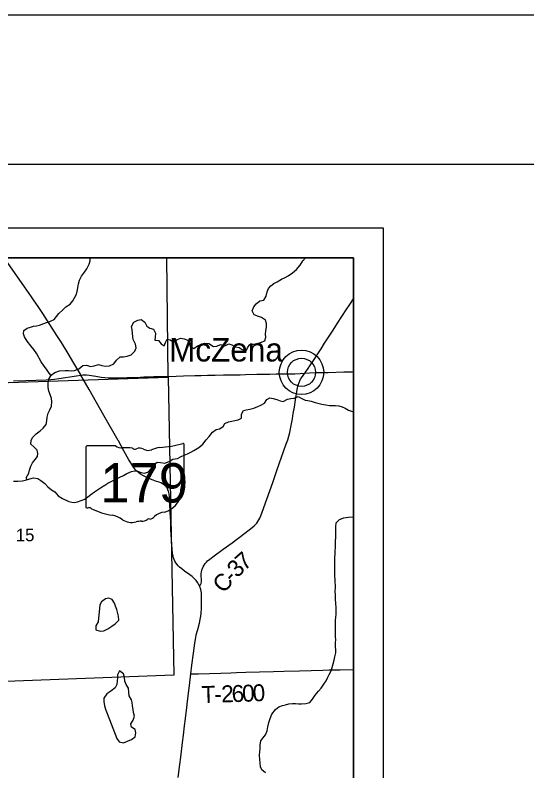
# Model space of a CAD drawing. Extents: x 0 to 34, y 0 to 22.
# Drawn here: x 7.526 to 9.242, y 19.466 to 22 of the extents above; entities that cross this region are included whole.
import ezdxf

# ---------------------------------------------------------------- set-up
doc = ezdxf.new("R2010")
doc.units = 0
for name, color, linetype in [('GM_X_Corporation', 7, 'Continuous'), ('GM_X_Corporation_Text', 7, 'Continuous'), ('GM_X_County_Road', 7, 'Continuous'), ('GM_X_County_Road_Text', 7, 'Continuous'), ('GM_X_Interchange_Ramps', 7, 'Continuous'), ('GM_X_Major_River_Text', 7, 'Continuous'), ('GM_X_Minor_River_Text', 7, 'Continuous'), ('GM_X_Rail_Line', 7, 'Continuous'), ('GM_X_Section_Text', 7, 'Continuous'), ('GM_X_State_Location', 7, 'Continuous'), ('GM_X_State_Route', 7, 'Continuous'), ('GM_X_Township_Road', 7, 'Continuous'), ('GM_X_Township_Text', 7, 'Continuous'), ('SH_Border', 7, 'Continuous'), ('SH_Cut_Line', 7, 'Continuous'), ('SH_Data', 7, 'Continuous')]:
    doc.layers.add(name, color=color, linetype=linetype)

msp = doc.modelspace()

# ---------------------------------------------------------------- linework, layer by layer
at = {"layer": 'GM_X_Corporation_Text'}
msp.add_line((8.4865, 20.8023), (8.4865, 20.8023), dxfattribs=at)
at = {"layer": 'GM_X_County_Road'}
for p, q in [((7.7634, 20.5519), (7.7634, 20.3518)), ((7.8632, 20.5554), (7.7666, 20.5554)), ((8.093, 20.4556), (8.093, 20.5603)), ((8.0929, 20.4557), (8.093, 20.4556))]:
    msp.add_line(p, q, dxfattribs=at)
for points in [[(7.8725, 20.5724), (7.8715, 20.5742), (7.824, 20.658), (7.7993, 20.7011), (7.7747, 20.7444), (7.7546, 20.7794), (7.7468, 20.793), (7.7453, 20.7956), (7.7234, 20.8332), (7.7041, 20.8651), (7.6814, 20.9022), (7.6667, 20.9259), (7.6194, 20.999), (7.6056, 21.0197), (7.5883, 21.0455), (7.5814, 21.0558), (7.5582, 21.0889), (7.5403, 21.1143), (7.5187, 21.1447), (7.5008, 21.17), (7.4888, 21.1866)], [(8.0729, 19.4442), (8.0782, 19.4873), (8.0814, 19.512), (8.0874, 19.5614), (8.0905, 19.586), (8.0942, 19.6169), (8.0973, 19.6415), (8.1016, 19.6785), (8.1044, 19.7001), (8.1109, 19.7525), (8.1156, 19.791), (8.1192, 19.8204), (8.1245, 19.8604), (8.1289, 19.8944), (8.1318, 19.9128), (8.1337, 19.922), (8.1384, 19.9401), (8.1442, 19.961), (8.1471, 19.9731), (8.1493, 19.9852), (8.1504, 19.9944), (8.1512, 20.0099), (8.1516, 20.0347), (8.1514, 20.0534), (8.1509, 20.0626), (8.1501, 20.0687), (8.1488, 20.0747), (8.1469, 20.0805), (8.1449, 20.0857), (8.1416, 20.0915), (8.1384, 20.0968), (8.1329, 20.1043), (8.1289, 20.1089), (8.1246, 20.1132), (8.1199, 20.1173), (8.1125, 20.1228), (8.0948, 20.1354), (8.0849, 20.143), (8.0777, 20.1491), (8.0733, 20.1535), (8.0692, 20.1583), (8.0655, 20.1634), (8.0622, 20.1688), (8.0595, 20.1745), (8.0573, 20.1804), (8.0557, 20.1864), (8.054, 20.1957), (8.0526, 20.2081), (8.0514, 20.2267), (8.0497, 20.2577), (8.0488, 20.2763), (8.0479, 20.3012), (8.0463, 20.3322), (8.0449, 20.3633), (8.0438, 20.385), (8.0428, 20.3942), (8.0417, 20.4002), (8.0409, 20.4031), (8.0387, 20.4088), (8.0374, 20.4116), (8.0358, 20.4142), (8.0341, 20.4167), (8.0323, 20.4191), (8.028, 20.4234), (8.0257, 20.4254), (8.0207, 20.4288), (8.0152, 20.4316), (8.0095, 20.4339), (8.0007, 20.4368), (7.9888, 20.4404), (7.9801, 20.4436), (7.9715, 20.4473), (7.9632, 20.4516), (7.955, 20.4563), (7.9472, 20.4614), (7.9397, 20.467), (7.935, 20.4712), (7.9305, 20.4756), (7.9265, 20.4804), (7.9209, 20.4879), (7.9141, 20.4984), (7.9078, 20.5092), (7.8912, 20.5389), (7.8725, 20.5724)]]:
    msp.add_lwpolyline(points, dxfattribs=at)
for centre, major_axis, start_param, end_param in [((7.7672, 20.5523), (0.00382, 0), 1.712693, 3.28349), ((7.8861, 20.5786), (0.037, 0), 4.042523, 4.731795), ((7.9756, 20.8282), (0.3495, 0), 4.814394, 5.042369), ((8.0893, 20.5608), (0.00367, 0), 6.141152, 7.989035), ((7.8984, 20.443), (0.133, 0), 1.404758, 1.657858), ((7.9286, 20.5534), (0.0107, 0), 3.836095, 5.185415), ((7.9443, 20.5302), (0.0222, 0), 0.950623, 2.079405), ((7.973, 20.562), (0.0267, 0), 4.081561, 5.145723), ((8.0201, 20.4942), (0.0703, 0), 1.699011, 2.107814), ((8.0921, 20.4479), (0.00568, 0), 1.883978, 3.671073), ((8.0891, 20.4552), (0.00393, 0), 5.05454, 6.418171), ((8.1061, 20.4118), (0.0248, 0), 2.387724, 3.262537), ((8.056, 20.4347), (0.0341, 0), 5.934695, 6.695948), ((7.9951, 20.3985), (0.0874, 0), 5.101752, 6.440018), ((7.7672, 20.3514), (0.00385, 0), 3.00124, 4.508301), ((7.7678, 20.3718), (0.0294, 0), 4.665946, 4.897461), ((7.7738, 20.3402), (0.0106, 0), 0.519207, 1.627899), ((7.9076, 20.52), (0.2524, 0), 4.195997, 4.488961), ((7.8324, 20.2619), (0.079, 0), 0.823519, 1.323587), ((8.032, 20.2956), (0.0479, 0), 1.647645, 2.488434), ((7.9178, 20.3393), (0.0501, 0), 4.026481, 4.996735), ((7.9467, 20.2701), (0.0412, 0), 1.495662, 1.94098), ((7.9504, 20.3243), (0.0267, 0), 4.691044, 5.507374), ((7.9746, 20.3049), (0.00752, 0), 1.147584, 2.315152), ((7.9713, 20.3324), (0.0282, 0), 4.937069, 5.64225)]:
    msp.add_ellipse(centre, major_axis=major_axis, ratio=0.8, start_param=start_param, end_param=end_param, dxfattribs=at)
at = {"layer": 'GM_X_County_Road_Text'}
msp.add_line((8.6543, 20.6725), (8.6602, 20.6699), dxfattribs=at)
for points in [[(7.6468, 20.7918), (7.6404, 20.7996), (7.6316, 20.8132), (7.624, 20.8234), (7.6133, 20.8374), (7.5988, 20.8647), (7.5889, 20.8783), (7.5786, 20.8912), (7.5664, 20.9063), (7.5576, 20.9211), (7.5549, 20.9317), (7.556, 20.9427), (7.5666, 20.9507), (7.5779, 20.9542), (7.5882, 20.9569), (7.5984, 20.958), (7.6086, 20.9607), (7.6222, 20.9657), (7.6321, 20.9692), (7.6423, 20.973), (7.6574, 20.9795), (7.6657, 20.989), (7.6733, 20.9997), (7.6857, 21.0107), (7.697, 21.0218), (7.711, 21.031), (7.7197, 21.0416), (7.7257, 21.0523), (7.7306, 21.0618), (7.734, 21.0732), (7.7366, 21.0861), (7.7388, 21.0986), (7.7425, 21.1108), (7.7485, 21.1252), (7.7591, 21.1385), (7.7666, 21.1488), (7.7749, 21.1652), (7.7779, 21.1766), (7.7775, 21.1866)], [(8.3252, 20.8966), (8.3354, 20.8986), (8.3494, 20.9021), (8.363, 20.9082), (8.3671, 20.9203), (8.3663, 20.9306), (8.3674, 20.9416), (8.3693, 20.9534), (8.3692, 20.9663), (8.3658, 20.9773), (8.3528, 20.9856), (8.3422, 20.9897), (8.3282, 20.9953), (8.3209, 21.0082), (8.3262, 21.0219), (8.3348, 21.0325), (8.3469, 21.0421), (8.3602, 21.0444), (8.3681, 21.0581), (8.3718, 21.0722), (8.3759, 21.0832), (8.3831, 21.0927), (8.3933, 21.0996), (8.4046, 21.1053), (8.4194, 21.1145), (8.4319, 21.1202), (8.4417, 21.1263), (8.4561, 21.1355), (8.4697, 21.1469), (8.4821, 21.1621), (8.4904, 21.1762), (8.4993, 21.1866)], [(7.5671, 20.4423), (7.5634, 20.449), (7.5724, 20.4646), (7.5742, 20.4741), (7.5795, 20.4874), (7.5851, 20.4984), (7.5942, 20.5102), (7.601, 20.5205), (7.6028, 20.5307), (7.6009, 20.5414), (7.5887, 20.5527), (7.5788, 20.5618), (7.5799, 20.5735), (7.5848, 20.5838), (7.5965, 20.5956), (7.6101, 20.6059), (7.621, 20.6151), (7.6305, 20.6276), (7.6331, 20.6401), (7.6338, 20.6515), (7.6375, 20.6652), (7.6428, 20.6766), (7.6484, 20.6888), (7.6495, 20.7043), (7.6479, 20.7142), (7.6456, 20.7244), (7.6399, 20.7388), (7.6368, 20.751), (7.6371, 20.7658), (7.6397, 20.7791), (7.6476, 20.7931), (7.6593, 20.8019), (7.6752, 20.8073), (7.6945, 20.8085), (7.7055, 20.8082), (7.7161, 20.8078), (7.726, 20.8082), (7.74, 20.8144), (7.7532, 20.8247), (7.7653, 20.8258), (7.7797, 20.8221), (7.7915, 20.8244), (7.8055, 20.8287), (7.8176, 20.8253), (7.8294, 20.8234), (7.843, 20.8242), (7.8574, 20.8311), (7.8664, 20.8433), (7.8785, 20.8547), (7.8895, 20.8548), (7.902, 20.856), (7.916, 20.8606), (7.9277, 20.8735), (7.9318, 20.8842), (7.9295, 20.8967), (7.9222, 20.9122), (7.9207, 20.9217), (7.9199, 20.9331), (7.9187, 20.9456), (7.9171, 20.9558), (7.9239, 20.9703), (7.9383, 20.9775), (7.9492, 20.9795), (7.9614, 20.9704), (7.9679, 20.9575), (7.9782, 20.95), (7.9907, 20.947), (7.9968, 20.9337), (7.9954, 20.9201), (7.9946, 20.9102), (8.0075, 20.9095), (8.0159, 20.8974), (8.0262, 20.8906), (8.0311, 20.902), (8.0356, 20.9134), (8.0462, 20.9115), (8.0568, 20.9047), (8.0693, 20.912), (8.0818, 20.9166), (8.0935, 20.9147), (8.1049, 20.9106), (8.1103, 20.9), (8.1133, 20.8894), (8.1251, 20.8822), (8.1376, 20.8914), (8.1516, 20.8956), (8.1626, 20.8998), (8.1758, 20.8995), (8.191, 20.8893), (8.2024, 20.8905), (8.2153, 20.8951), (8.2289, 20.891), (8.2433, 20.8982), (8.2528, 20.8949), (8.2657, 20.8881), (8.2775, 20.8858), (8.2873, 20.8787), (8.3006, 20.8749), (8.3059, 20.8844), (8.313, 20.8955), (8.3252, 20.8966)], [(7.5213, 20.4375), (7.5361, 20.4371), (7.5513, 20.4383), (7.5642, 20.4414), (7.5763, 20.4453), (7.5876, 20.4487), (7.6028, 20.4461), (7.6127, 20.4397), (7.626, 20.4291), (7.6366, 20.4189), (7.6484, 20.408), (7.6598, 20.4012), (7.6712, 20.3887), (7.6849, 20.3796), (7.7062, 20.3691), (7.7161, 20.3665), (7.7255, 20.3661), (7.7361, 20.3684), (7.7479, 20.3727), (7.7596, 20.3773), (7.7702, 20.3853), (7.7804, 20.3925), (7.7925, 20.402), (7.8027, 20.4085), (7.8125, 20.415), (7.8269, 20.4242), (7.8378, 20.4311), (7.8503, 20.4376), (7.8632, 20.4437), (7.8775, 20.4506), (7.8896, 20.4559), (7.9014, 20.4628), (7.9161, 20.4701), (7.9267, 20.472), (7.9362, 20.4705), (7.9491, 20.4664), (7.9586, 20.4641), (7.9718, 20.468), (7.9831, 20.4813), (7.9903, 20.492), (8.0031, 20.5007), (8.0141, 20.5004), (8.0278, 20.4978), (8.0429, 20.5036), (8.0554, 20.5108), (8.0706, 20.5139), (8.083, 20.5196), (8.0936, 20.5242), (8.1046, 20.5288), (8.1156, 20.535), (8.1254, 20.5403), (8.142, 20.5502), (8.1552, 20.562), (8.1669, 20.5757), (8.1764, 20.5876), (8.1877, 20.6016), (8.2001, 20.6108), (8.2115, 20.6123), (8.2236, 20.6207), (8.2296, 20.6306), (8.2421, 20.6364), (8.2531, 20.6387), (8.2633, 20.641), (8.2743, 20.6433), (8.2849, 20.6491), (8.2856, 20.662), (8.2916, 20.6738), (8.3014, 20.6764), (8.3128, 20.6784), (8.3264, 20.6822), (8.3401, 20.688), (8.3506, 20.6918), (8.3624, 20.6987), (8.3699, 20.7112), (8.3805, 20.7166), (8.3911, 20.7144), (8.4036, 20.711), (8.4154, 20.7072), (8.4253, 20.7042), (8.4392, 20.7123), (8.451, 20.7146), (8.4623, 20.7161), (8.4756, 20.7215), (8.4858, 20.7155), (8.4984, 20.7087), (8.5079, 20.708), (8.5185, 20.7061), (8.5318, 20.7012), (8.5416, 20.6986), (8.5545, 20.696), (8.5682, 20.6938), (8.5799, 20.6915), (8.5898, 20.6908), (8.6004, 20.6909), (8.6114, 20.6901), (8.6224, 20.6868), (8.6323, 20.6822), (8.6437, 20.6751), (8.6543, 20.6725)], [(8.6019, 19.8617), (8.6011, 19.8715), (8.6003, 19.8821), (8.6006, 19.895), (8.601, 19.9064), (8.6009, 19.9159), (8.6007, 19.9709), (8.6014, 19.9804), (8.6021, 19.9918), (8.6025, 20.0032), (8.6024, 20.0142), (8.6012, 20.0271), (8.6004, 20.0419), (8.6, 20.0567), (8.5995, 20.0681), (8.5999, 20.0802), (8.5998, 20.1064), (8.5986, 20.1193), (8.5985, 20.1322), (8.5981, 20.1432), (8.5979, 20.18), (8.599, 20.1945), (8.5994, 20.2047), (8.6001, 20.2142), (8.6, 20.2244), (8.6008, 20.2351), (8.6018, 20.2491), (8.6014, 20.2632), (8.601, 20.2749), (8.6017, 20.2848), (8.6028, 20.2973), (8.6133, 20.3091), (8.6281, 20.3141), (8.6436, 20.3168), (8.6592, 20.3173), (8.6602, 20.3172)], [(8.3656, 19.46), (8.3538, 19.4698), (8.3488, 19.4801), (8.348, 19.493), (8.3468, 19.5047), (8.3452, 19.5172), (8.3467, 19.5305), (8.3482, 19.54), (8.3481, 19.5522), (8.35, 19.5662), (8.3567, 19.5757), (8.3658, 19.5872), (8.3714, 19.6005), (8.374, 19.6134), (8.3774, 19.6278), (8.3811, 19.6415), (8.3871, 19.6567), (8.3988, 19.6719), (8.4109, 19.6811), (8.423, 19.6849), (8.4332, 19.688), (8.4442, 19.6907), (8.4563, 19.6919), (8.4662, 19.6915), (8.4768, 19.6908), (8.4866, 19.6904), (8.501, 19.6916), (8.5143, 19.6955), (8.523, 19.7061), (8.532, 19.7195), (8.5429, 19.7332), (8.552, 19.7431), (8.561, 19.7564), (8.5686, 19.7682), (8.575, 19.78), (8.5795, 19.7895), (8.5843, 19.7994), (8.5888, 19.8123), (8.5926, 19.8248), (8.5959, 19.8377), (8.5978, 19.848), (8.6019, 19.8617)]]:
    msp.add_lwpolyline(points, dxfattribs=at)
at = {"layer": 'GM_X_Interchange_Ramps'}
msp.add_lwpolyline([(8.1156, 19.791), (8.1222, 19.7911), (8.1409, 19.7914), (8.1782, 19.7926), (8.2155, 19.7939), (8.2497, 19.7953), (8.2683, 19.7958), (8.2994, 19.7967), (8.346, 19.7978), (8.3927, 19.7989), (8.4269, 19.8), (8.4797, 19.8015), (8.5575, 19.8038), (8.5792, 19.8045), (8.6166, 19.8052), (8.6602, 19.8064)], dxfattribs=at)
at = {"layer": 'GM_X_Minor_River_Text'}
for points in [[(7.8052, 19.9661), (7.7973, 19.9524), (7.797, 19.9387), (7.8114, 19.935), (7.8236, 19.9361), (7.8376, 19.9423), (7.8504, 19.9514), (7.8617, 19.9594), (7.8742, 19.9716), (7.8734, 19.9853), (7.8699, 19.9978), (7.8672, 20.0073), (7.863, 20.0186), (7.8596, 20.0281), (7.8516, 20.0406), (7.8409, 20.0451), (7.8292, 20.0428), (7.8156, 20.0325), (7.8103, 20.0222)], [(7.8103, 20.0222), (7.8052, 19.9661)], [(7.8675, 19.575), (7.8755, 19.5629), (7.8903, 19.5596), (7.9035, 19.5653), (7.9164, 19.5714), (7.9292, 19.5806), (7.9315, 19.5939), (7.9291, 19.6045), (7.9162, 19.6124), (7.9139, 19.6234), (7.9226, 19.6363), (7.9267, 19.6489), (7.9236, 19.6614), (7.922, 19.6716), (7.9201, 19.6841), (7.9185, 19.6948), (7.9166, 19.7042), (7.909, 19.7175), (7.9082, 19.73), (7.907, 19.7429), (7.8986, 19.7558), (7.894, 19.7671), (7.8936, 19.7793), (7.8893, 19.7918), (7.8764, 19.8012), (7.87, 19.7883), (7.8697, 19.7784), (7.869, 19.7667), (7.8675, 19.756), (7.8619, 19.7446), (7.8475, 19.7328), (7.8343, 19.7248), (7.8237, 19.7103), (7.8234, 19.6986), (7.8257, 19.6842), (7.83, 19.6698), (7.8349, 19.6584)], [(7.8349, 19.6584), (7.8675, 19.575)]]:
    msp.add_lwpolyline(points, dxfattribs=at)
at = {"layer": 'GM_X_Rail_Line'}
for radius in [0.0744, 0.0472]:
    msp.add_circle((8.4865, 20.8023), radius, dxfattribs=at)
at = {"layer": 'GM_X_State_Route'}
for points in [[(8.6602, 18.8038), (8.6602, 21.1866), (4.0708, 21.1866), (4.0805, 19.8173), (4.0805, 19.8117), (4.0945, 18.7432), (4.5791, 18.7479), (5.5804, 18.7605), (5.5812, 18.7605), (6.0902, 18.7638), (7.082, 18.7532), (7.9519, 18.7787), (8.0539, 18.7796), (8.5878, 18.803)], [(8.0346, 21.1866), (7.0587, 21.1866), (7.0675, 20.7541), (8.0394, 20.7862)], [(7.0675, 20.7541), (8.0394, 20.7862), (8.0588, 19.7873), (7.0797, 19.7498)]]:
    msp.add_lwpolyline(points, close=True, dxfattribs=at)
at = {"layer": 'GM_X_Township_Road'}
for points in [[(8.4976, 20.7996), (8.4992, 20.8018), (8.5065, 20.8118), (8.5169, 20.8271), (8.5269, 20.8424), (8.5387, 20.8605), (8.552, 20.8815), (8.5637, 20.8998), (8.5923, 20.9441), (8.6075, 20.9675), (8.6363, 21.0116), (8.6481, 21.0298), (8.6602, 21.0489)], [(8.4976, 20.7996), (8.5135, 20.8007), (8.5353, 20.8014), (8.5539, 20.8018), (8.5757, 20.8022), (8.6284, 20.8036), (8.6563, 20.8045), (8.6602, 20.8046)], [(7.5215, 20.7734), (7.5619, 20.7746), (7.596, 20.7757), (7.6302, 20.7772), (7.6457, 20.7781), (7.658, 20.7792), (7.6734, 20.7813), (7.7317, 20.7907), (7.7468, 20.793)], [(7.7468, 20.793), (7.7533, 20.7937), (7.7596, 20.7938), (7.7658, 20.7935), (7.7752, 20.7924), (7.7967, 20.7889), (7.8151, 20.7861), (7.8274, 20.7847), (7.8397, 20.7839), (7.8583, 20.7835), (7.8801, 20.7837), (7.9018, 20.7845), (7.9173, 20.7852), (7.9451, 20.7863), (7.9575, 20.7867), (7.973, 20.7872), (7.9917, 20.7878), (8.0258, 20.7886), (8.0662, 20.7899), (8.0911, 20.7907), (8.1284, 20.7917), (8.1502, 20.7921), (8.1719, 20.7927), (8.1967, 20.7931), (8.2247, 20.7935), (8.2526, 20.7939), (8.2806, 20.7943), (8.2992, 20.7947), (8.3365, 20.7956), (8.38, 20.7966), (8.4018, 20.7968), (8.4204, 20.7969), (8.4453, 20.7972), (8.4639, 20.7976), (8.4825, 20.7984), (8.4976, 20.7996)], [(8.1449, 20.0857), (8.148, 20.0898), (8.1499, 20.0948), (8.151, 20.1013), (8.1507, 20.1087), (8.1505, 20.118), (8.1506, 20.1272), (8.1512, 20.1333), (8.1523, 20.1393), (8.1532, 20.1422), (8.1543, 20.1451), (8.1569, 20.1506), (8.16, 20.1559), (8.1636, 20.1609), (8.1675, 20.1656), (8.1718, 20.1699), (8.1789, 20.1759), (8.1937, 20.1871), (8.224, 20.2089), (8.2541, 20.231), (8.2964, 20.2626), (8.3211, 20.2815), (8.3282, 20.2877), (8.3326, 20.2921), (8.3367, 20.2969), (8.3405, 20.3019), (8.3437, 20.3073), (8.3466, 20.3129), (8.3505, 20.3214), (8.355, 20.333), (8.3705, 20.377), (8.39, 20.4327), (8.4053, 20.4768), (8.4342, 20.5588), (8.4403, 20.5765), (8.4439, 20.5884), (8.4471, 20.6004), (8.4497, 20.6126), (8.4558, 20.6461), (8.459, 20.6644), (8.4628, 20.6858), (8.4666, 20.7103), (8.4702, 20.7318), (8.4735, 20.7501), (8.4755, 20.7591), (8.4782, 20.768), (8.4804, 20.7737), (8.4832, 20.7791), (8.4865, 20.7843), (8.4918, 20.7918), (8.4976, 20.7996)]]:
    msp.add_lwpolyline(points, dxfattribs=at)
at = {"layer": 'SH_Border'}
msp.add_lwpolyline([(1.5, 21.5), (33.5, 21.5), (33.5, 0.5), (1.5, 0.5)], close=True, dxfattribs=at)
at = {"layer": 'SH_Cut_Line'}
msp.add_lwpolyline([(0, 0), (34, 0), (34, 22), (0, 22)], close=True, dxfattribs=at)
at = {"layer": 'SH_Data'}
for points in [[(1.7602, 21.2866), (8.7602, 21.2866), (8.7602, 14.2866), (1.7602, 14.2866)], [(1.8602, 21.1866), (8.6602, 21.1866), (8.6602, 14.3866), (1.8602, 14.3866)]]:
    msp.add_lwpolyline(points, close=True, dxfattribs=at)

# ---------------------------------------------------------------- texts
at = {"layer": 'GM_X_Corporation'}
msp.add_text('McZena', height=0.07898, rotation=0, dxfattribs=at).set_placement((8.0426, 20.8386))
at = {"layer": 'GM_X_County_Road'}
msp.add_text('179', height=0.13184, dxfattribs=at).set_placement((7.8119, 20.3659))
at = {"layer": 'GM_X_Major_River_Text'}
msp.add_text('179', height=0.000189, rotation=0, dxfattribs=at).set_placement((7.8576, 20.4248))
for s in ['s', 'r']:
    msp.add_text(s, height=0.000189, dxfattribs=at).set_placement((7.9245, 20.4386))
at = {"layer": 'GM_X_Section_Text'}
for s, rotation, p in [('7', 41.3656, (8.2949, 20.135)), ('3', 45.6072, (8.2712, 20.1108)), ('C', 49.3619, (8.226, 20.0587)), ('-', 48.3191, (8.2562, 20.0939))]:
    msp.add_text(s, height=0.0568, rotation=rotation, dxfattribs=at).set_placement(p)
at = {"layer": 'GM_X_State_Location'}
msp.add_text('15', height=0.04186, rotation=0, dxfattribs=at).set_placement((7.5289, 20.2359))
at = {"layer": 'GM_X_Township_Text'}
for s, rotation, p in [('T', 1.7017, (8.1522, 19.6934)), ('2', 1.7074, (8.218, 19.6954)), ('6', 1.7317, (8.253, 19.6964)), ('0', 1.8356, (8.2881, 19.6975)), ('0', 2.2895, (8.3236, 19.6986)), ('-', 1.6941, (8.1947, 19.6947))]:
    msp.add_text(s, height=0.0568, rotation=rotation, dxfattribs=at).set_placement(p)

doc.saveas('drawing.dxf')
